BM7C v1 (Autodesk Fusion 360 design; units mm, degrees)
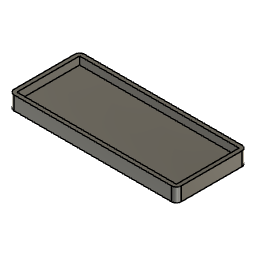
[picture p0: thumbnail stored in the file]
sketch "Sketch1" plane through (0, 0, 0) normal (0, 0, 1) x axis (1, 0, 0)
  line L1 (81.5, 0) -> (0, 0)
  line L2 (81.5, 32) -> (81.5, 0)
  line L3 (0, 32) -> (81.5, 32)
  line L4 (0, 0) -> (0, 32)
  line L5 (83.5, -2) -> (-2, -2)
  line L6 (83.5, 34) -> (83.5, -2)
  line L7 (-2, 34) -> (83.5, 34)
  line L8 (-2, -2) -> (-2, 34)
  point P1 (0, 0)
  point P2 (0, 0)
  point P3 (81.5, 0)
  point P5 (0, 32)
  horizontal L1
  vertical L2
  horizontal L3
  vertical L4
  coincident P1 P2
  dimension "d1" distance P2 P3 = 81.5
  dimension "d2" distance P2 P5 = 32
  dimension "d3" = 2
extrude "Extrude1" new body sketch "Sketch1" against normal blind 7
extrude "Extrude2" cut sketch "Sketch1" profile of L1 L2 L3 L4 against normal blind 4
fillet "Fillet1" radius 2.5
